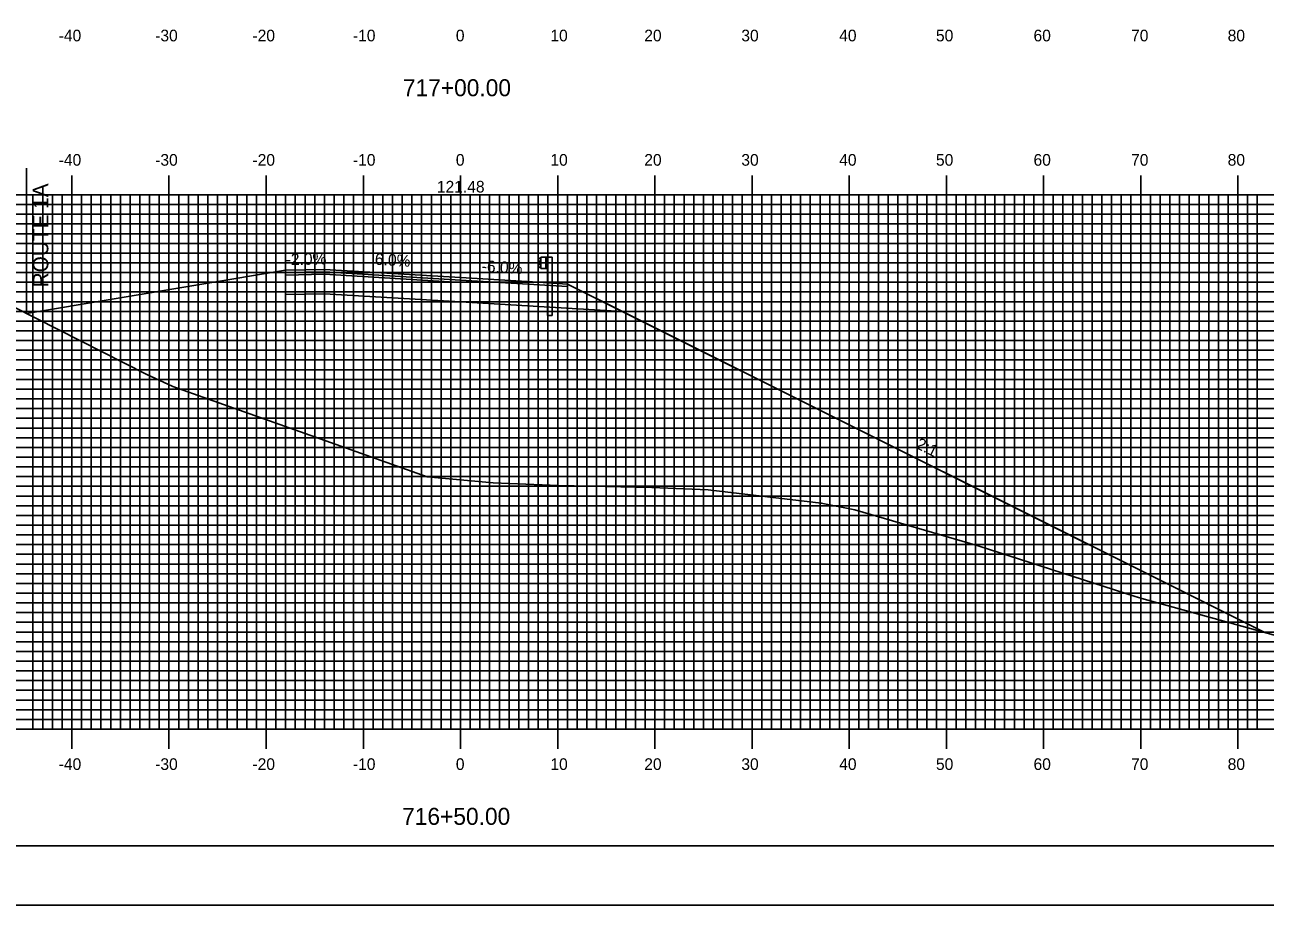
# Model space of a CAD drawing. Extents: x 856871 to 857214, y 364366 to 364586.
# Drawn here: x 856992 to 857119.6, y 364365.7 to 364456.3 of the extents above; entities that cross this region are included whole.
import ezdxf

# ---------------------------------------------------------------- set-up
doc = ezdxf.new("R2010")
doc.units = 0
for name, color, linetype in [('ANNOTATION', 7, 'Continuous'), ('BORDER', 7, 'Continuous'), ('D_Guardrail_Beam_Rt', 7, 'Continuous'), ('D_Roadway_Centerline', 7, 'Continuous'), ('D_Roadway_Centerline_Text', 7, 'Continuous'), ('D_Roadway_Edge_Shoulder', 7, 'Continuous'), ('D_Roadway_Edge_TW', 7, 'Continuous'), ('D_Roadway_Pavement', 7, 'Continuous'), ('D_Roadway_SlopeLines', 7, 'Continuous'), ('D_Roadway_SubGrade', 7, 'Continuous'), ('H_V ANNOTATION', 7, 'Continuous'), ('MAJOR', 7, 'Continuous'), ('MINOR', 7, 'Continuous'), ('PLOT BOUNDARY', 7, 'Continuous'), ('S_Roadway_Centerline', 7, 'Continuous')]:
    doc.layers.add(name, color=color, linetype=linetype)

msp = doc.modelspace()

# ---------------------------------------------------------------- linework, layer by layer
at = {"layer": 'BORDER'}
msp.add_lwpolyline([(856887.22, 364371.79), (857207.22, 364371.79), (857207.22, 364581.79), (856887.22, 364581.79)], close=True, dxfattribs=at)
at = {"layer": 'D_Guardrail_Beam_Rt'}
for p, q in [((857045, 364432.27), (857044.86, 364432.17)), ((857045.09, 364432.29), (857045.02, 364432.27)), ((857045.09, 364432.37), (857045.78, 364432.37)), ((857045.09, 364431.2), (857045.09, 364432.37)), ((857045.61, 364432.37), (857045.61, 364431.2)), ((857045.72, 364432.37), (857045.72, 364431.2)), ((857045.78, 364432.37), (857046.25, 364432.37)), ((857045.78, 364432.37), (857045.78, 364431.2)), ((857046.25, 364432.37), (857046.25, 364426.37)), ((857044.86, 364432.02), (857045.06, 364431.89)), ((857045.06, 364431.69), (857044.86, 364431.55)), ((857044.86, 364431.41), (857045, 364431.31)), ((857045.02, 364431.3), (857045.09, 364431.29)), ((857045.09, 364431.82), (857045.09, 364431.75)), ((857045.78, 364431.2), (857045.09, 364431.2)), ((857045.76, 364426.37), (857045.76, 364431.2)), ((857045.76, 364426.37), (857046.25, 364426.37))]:
    msp.add_line(p, q, dxfattribs=at)
for centre, major_axis, start_param, end_param in [((857045.03, 364432.23), (-0.0417, 0), 4.907132, 5.323254), ((857044.91, 364432.09), (-0.0877, 0), 5.323254, 7.243116), ((857044.91, 364431.48), (-0.0877, 0), 5.323254, 7.243116), ((857045.03, 364431.34), (-0.0417, 0), 0.959931, 1.376053), ((857045.01, 364431.82), (0.0789, 0), 0, 0.959931), ((857045.01, 364431.75), (0.0789, 0), 5.323254, 6.283185)]:
    msp.add_ellipse(centre, major_axis=major_axis, ratio=0.995501, start_param=start_param, end_param=end_param, dxfattribs=at)
at = {"layer": 'D_Roadway_Centerline'}
msp.add_lwpolyline([(857018.82, 364431.03), (857022.82, 364431.11), (857036.82, 364430.27), (857044.82, 364429.79), (857047.82, 364429.61), (857053.5, 364426.77), (857119.44, 364393.8)], dxfattribs=at)
at = {"layer": 'D_Roadway_Edge_Shoulder'}
for points in [[(857022.82, 364431.11), (857018.82, 364431.03), (857018.82, 364430.78), (857022.82, 364430.86)], [(857036.82, 364430.27), (857044.82, 364429.79), (857044.82, 364429.79), (857047.82, 364429.61), (857047.82, 364429.36), (857036.82, 364430.02)]]:
    msp.add_lwpolyline(points, close=True, dxfattribs=at)
at = {"layer": 'D_Roadway_Edge_TW'}
msp.add_lwpolyline([(857022.82, 364431.11), (857036.82, 364430.27), (857036.82, 364430.02), (857022.82, 364430.86)], close=True, dxfattribs=at)
at = {"layer": 'D_Roadway_Pavement'}
for points in [[(857022.82, 364430.86), (857018.82, 364430.78), (857018.82, 364430.53), (857022.82, 364430.61)], [(857022.82, 364430.86), (857036.82, 364430.02), (857036.82, 364429.77), (857022.82, 364430.61)]]:
    msp.add_lwpolyline(points, close=True, dxfattribs=at)
msp.add_lwpolyline([(857036.82, 364430.02), (857036.82, 364429.77)], dxfattribs=at)
msp.add_lwpolyline([(857036.82, 364430.02), (857036.82, 364429.77)], dxfattribs=at)
at = {"layer": 'D_Roadway_SlopeLines'}
for points in [[(857018.82, 364431.03), (856992.14, 364426.58)], [(857047.82, 364429.61), (857119.44, 364393.8)]]:
    msp.add_lwpolyline(points, dxfattribs=at)
at = {"layer": 'D_Roadway_SubGrade'}
msp.add_line((856992.14, 364441.54), (856992.14, 364426.58), dxfattribs=at)
for points in [[(857022.82, 364430.61), (857018.82, 364430.53), (857018.82, 364430.78), (857018.82, 364431.03), (857018.82, 364428.53), (857022.82, 364428.61)], [(857022.82, 364430.61), (857036.82, 364429.77), (857036.82, 364427.77), (857022.82, 364428.61)], [(857036.82, 364429.77), (857036.82, 364430.02), (857047.82, 364429.36), (857047.82, 364429.61), (857053.5, 364426.77), (857036.82, 364427.77)]]:
    msp.add_lwpolyline(points, close=True, dxfattribs=at)
at = {"layer": 'MAJOR'}
for p, q in [((856996.82, 364440.79), (856996.82, 364438.79)), ((857006.82, 364440.79), (857006.82, 364438.79)), ((857016.82, 364440.79), (857016.82, 364438.79)), ((857026.82, 364440.79), (857026.82, 364438.79)), ((857036.82, 364440.79), (857036.82, 364438.79)), ((857046.82, 364440.79), (857046.82, 364438.79)), ((857056.82, 364440.79), (857056.82, 364438.79)), ((857066.82, 364440.79), (857066.82, 364438.79)), ((857076.82, 364440.79), (857076.82, 364438.79)), ((857086.82, 364440.79), (857086.82, 364438.79)), ((857096.82, 364440.79), (857096.82, 364438.79)), ((857106.82, 364440.79), (857106.82, 364438.79)), ((857116.82, 364440.79), (857116.82, 364438.79)), ((856896.82, 364438.79), (857176.82, 364438.79)), ((856896.82, 364438.79), (857176.82, 364438.79)), ((856996.82, 364383.79), (856996.82, 364438.79)), ((857006.82, 364383.79), (857006.82, 364438.79)), ((857016.82, 364383.79), (857016.82, 364438.79)), ((857026.82, 364383.79), (857026.82, 364438.79)), ((857036.82, 364383.79), (857036.82, 364438.79)), ((857046.82, 364383.79), (857046.82, 364438.79)), ((857056.82, 364383.79), (857056.82, 364438.79)), ((857066.82, 364383.79), (857066.82, 364438.79)), ((857076.82, 364383.79), (857076.82, 364438.79)), ((857086.82, 364383.79), (857086.82, 364438.79)), ((857096.82, 364383.79), (857096.82, 364438.79)), ((857106.82, 364383.79), (857106.82, 364438.79)), ((857116.82, 364383.79), (857116.82, 364438.79)), ((856896.82, 364433.79), (857176.82, 364433.79)), ((856896.82, 364428.79), (857176.82, 364428.79)), ((856896.82, 364423.79), (857176.82, 364423.79)), ((856896.82, 364418.79), (857176.82, 364418.79)), ((856896.82, 364413.79), (857176.82, 364413.79)), ((856896.82, 364408.79), (857176.82, 364408.79)), ((856896.82, 364403.79), (857176.82, 364403.79)), ((856896.82, 364398.79), (857176.82, 364398.79)), ((856896.82, 364393.79), (857176.82, 364393.79)), ((856896.82, 364388.79), (857176.82, 364388.79)), ((856896.82, 364383.79), (857176.82, 364383.79)), ((856896.82, 364383.79), (857176.82, 364383.79)), ((856996.82, 364381.78), (856996.82, 364383.79)), ((857006.82, 364381.78), (857006.82, 364383.79)), ((857016.82, 364381.78), (857016.82, 364383.79)), ((857026.82, 364381.78), (857026.82, 364383.79)), ((857036.82, 364381.78), (857036.82, 364383.79)), ((857046.82, 364381.78), (857046.82, 364383.79)), ((857056.82, 364381.78), (857056.82, 364383.79)), ((857066.82, 364381.78), (857066.82, 364383.79)), ((857076.82, 364381.78), (857076.82, 364383.79)), ((857086.82, 364381.78), (857086.82, 364383.79)), ((857096.82, 364381.78), (857096.82, 364383.79)), ((857106.82, 364381.78), (857106.82, 364383.79)), ((857116.82, 364381.78), (857116.82, 364383.79))]:
    msp.add_line(p, q, dxfattribs=at)
at = {"layer": 'MINOR'}
for p, q in [((856992.82, 364383.79), (856992.82, 364438.79)), ((856993.82, 364383.79), (856993.82, 364438.79)), ((856994.82, 364383.79), (856994.82, 364438.79)), ((856995.82, 364383.79), (856995.82, 364438.79)), ((856997.82, 364383.79), (856997.82, 364438.79)), ((856998.82, 364383.79), (856998.82, 364438.79)), ((856999.82, 364383.79), (856999.82, 364438.79)), ((857000.82, 364383.79), (857000.82, 364438.79)), ((857001.82, 364383.79), (857001.82, 364438.79)), ((857002.82, 364383.79), (857002.82, 364438.79)), ((857003.82, 364383.79), (857003.82, 364438.79)), ((857004.82, 364383.79), (857004.82, 364438.79)), ((857005.82, 364383.79), (857005.82, 364438.79)), ((857007.82, 364383.79), (857007.82, 364438.79)), ((857008.82, 364383.79), (857008.82, 364438.79)), ((857009.82, 364383.79), (857009.82, 364438.79)), ((857010.82, 364383.79), (857010.82, 364438.79)), ((857011.82, 364383.79), (857011.82, 364438.79)), ((857012.82, 364383.79), (857012.82, 364438.79)), ((857013.82, 364383.79), (857013.82, 364438.79)), ((857014.82, 364383.79), (857014.82, 364438.79)), ((857015.82, 364383.79), (857015.82, 364438.79)), ((857017.82, 364383.79), (857017.82, 364438.79)), ((857018.82, 364383.79), (857018.82, 364438.79)), ((857019.82, 364383.79), (857019.82, 364438.79)), ((857020.82, 364383.79), (857020.82, 364438.79)), ((857021.82, 364383.79), (857021.82, 364438.79)), ((857022.82, 364383.79), (857022.82, 364438.79)), ((857023.82, 364383.79), (857023.82, 364438.79)), ((857024.82, 364383.79), (857024.82, 364438.79)), ((857025.82, 364383.79), (857025.82, 364438.79)), ((857027.82, 364383.79), (857027.82, 364438.79)), ((857028.82, 364383.79), (857028.82, 364438.79)), ((857029.82, 364383.79), (857029.82, 364438.79)), ((857030.82, 364383.79), (857030.82, 364438.79)), ((857031.82, 364383.79), (857031.82, 364438.79)), ((857032.82, 364383.79), (857032.82, 364438.79)), ((857033.82, 364383.79), (857033.82, 364438.79)), ((857034.82, 364383.79), (857034.82, 364438.79)), ((857035.82, 364383.79), (857035.82, 364438.79)), ((857037.82, 364383.79), (857037.82, 364438.79)), ((857038.82, 364383.79), (857038.82, 364438.79)), ((857039.82, 364383.79), (857039.82, 364438.79)), ((857040.82, 364383.79), (857040.82, 364438.79)), ((857041.82, 364383.79), (857041.82, 364438.79)), ((857042.82, 364383.79), (857042.82, 364438.79)), ((857043.82, 364383.79), (857043.82, 364438.79)), ((857044.82, 364383.79), (857044.82, 364438.79)), ((857045.82, 364383.79), (857045.82, 364438.79)), ((857047.82, 364383.79), (857047.82, 364438.79)), ((857048.82, 364383.79), (857048.82, 364438.79)), ((857049.82, 364383.79), (857049.82, 364438.79)), ((857050.82, 364383.79), (857050.82, 364438.79)), ((857051.82, 364383.79), (857051.82, 364438.79)), ((857052.82, 364383.79), (857052.82, 364438.79)), ((857053.82, 364383.79), (857053.82, 364438.79)), ((857054.82, 364383.79), (857054.82, 364438.79)), ((857055.82, 364383.79), (857055.82, 364438.79)), ((857057.82, 364383.79), (857057.82, 364438.79)), ((857058.82, 364383.79), (857058.82, 364438.79)), ((857059.82, 364383.79), (857059.82, 364438.79)), ((857060.82, 364383.79), (857060.82, 364438.79)), ((857061.82, 364383.79), (857061.82, 364438.79)), ((857062.82, 364383.79), (857062.82, 364438.79)), ((857063.82, 364383.79), (857063.82, 364438.79)), ((857064.82, 364383.79), (857064.82, 364438.79)), ((857065.82, 364383.79), (857065.82, 364438.79)), ((857067.82, 364383.79), (857067.82, 364438.79)), ((857068.82, 364383.79), (857068.82, 364438.79)), ((857069.82, 364383.79), (857069.82, 364438.79)), ((857070.82, 364383.79), (857070.82, 364438.79)), ((857071.82, 364383.79), (857071.82, 364438.79)), ((857072.82, 364383.79), (857072.82, 364438.79)), ((857073.82, 364383.79), (857073.82, 364438.79)), ((857074.82, 364383.79), (857074.82, 364438.79)), ((857075.82, 364383.79), (857075.82, 364438.79)), ((857077.82, 364383.79), (857077.82, 364438.79)), ((857078.82, 364383.79), (857078.82, 364438.79)), ((857079.82, 364383.79), (857079.82, 364438.79)), ((857080.82, 364383.79), (857080.82, 364438.79)), ((857081.82, 364383.79), (857081.82, 364438.79)), ((857082.82, 364383.79), (857082.82, 364438.79)), ((857083.82, 364383.79), (857083.82, 364438.79)), ((857084.82, 364383.79), (857084.82, 364438.79)), ((857085.82, 364383.79), (857085.82, 364438.79)), ((857087.82, 364383.79), (857087.82, 364438.79)), ((857088.82, 364383.79), (857088.82, 364438.79)), ((857089.82, 364383.79), (857089.82, 364438.79)), ((857090.82, 364383.79), (857090.82, 364438.79)), ((857091.82, 364383.79), (857091.82, 364438.79)), ((857092.82, 364383.79), (857092.82, 364438.79)), ((857093.82, 364383.79), (857093.82, 364438.79)), ((857094.82, 364383.79), (857094.82, 364438.79)), ((857095.82, 364383.79), (857095.82, 364438.79)), ((857097.82, 364383.79), (857097.82, 364438.79)), ((857098.82, 364383.79), (857098.82, 364438.79)), ((857099.82, 364383.79), (857099.82, 364438.79)), ((857100.82, 364383.79), (857100.82, 364438.79)), ((857101.82, 364383.79), (857101.82, 364438.79)), ((857102.82, 364383.79), (857102.82, 364438.79)), ((857103.82, 364383.79), (857103.82, 364438.79)), ((857104.82, 364383.79), (857104.82, 364438.79)), ((857105.82, 364383.79), (857105.82, 364438.79)), ((857107.82, 364383.79), (857107.82, 364438.79)), ((857108.82, 364383.79), (857108.82, 364438.79)), ((857109.82, 364383.79), (857109.82, 364438.79)), ((857110.82, 364383.79), (857110.82, 364438.79)), ((857111.82, 364383.79), (857111.82, 364438.79)), ((857112.82, 364383.79), (857112.82, 364438.79)), ((857113.82, 364383.79), (857113.82, 364438.79)), ((857114.82, 364383.79), (857114.82, 364438.79)), ((857115.82, 364383.79), (857115.82, 364438.79)), ((857117.82, 364383.79), (857117.82, 364438.79)), ((857118.82, 364383.79), (857118.82, 364438.79)), ((856896.82, 364437.79), (857176.82, 364437.79)), ((856896.82, 364436.79), (857176.82, 364436.79)), ((856896.82, 364435.79), (857176.82, 364435.79)), ((856896.82, 364434.79), (857176.82, 364434.79)), ((856896.82, 364432.79), (857176.82, 364432.79)), ((856896.82, 364431.79), (857176.82, 364431.79)), ((856896.82, 364430.79), (857176.82, 364430.79)), ((856896.82, 364429.79), (857176.82, 364429.79)), ((856896.82, 364427.79), (857176.82, 364427.79)), ((856896.82, 364426.79), (857176.82, 364426.79)), ((856896.82, 364425.79), (857176.82, 364425.79)), ((856896.82, 364424.79), (857176.82, 364424.79)), ((856896.82, 364422.79), (857176.82, 364422.79)), ((856896.82, 364421.79), (857176.82, 364421.79)), ((856896.82, 364420.79), (857176.82, 364420.79)), ((856896.82, 364419.79), (857176.82, 364419.79)), ((856896.82, 364417.79), (857176.82, 364417.79)), ((856896.82, 364416.79), (857176.82, 364416.79)), ((856896.82, 364415.79), (857176.82, 364415.79)), ((856896.82, 364414.79), (857176.82, 364414.79)), ((856896.82, 364412.79), (857176.82, 364412.79)), ((856896.82, 364411.79), (857176.82, 364411.79)), ((856896.82, 364410.79), (857176.82, 364410.79)), ((856896.82, 364409.79), (857176.82, 364409.79)), ((856896.82, 364407.79), (857176.82, 364407.79)), ((856896.82, 364406.79), (857176.82, 364406.79)), ((856896.82, 364405.79), (857176.82, 364405.79)), ((856896.82, 364404.79), (857176.82, 364404.79)), ((856896.82, 364402.79), (857176.82, 364402.79)), ((856896.82, 364401.79), (857176.82, 364401.79)), ((856896.82, 364400.79), (857176.82, 364400.79)), ((856896.82, 364399.79), (857176.82, 364399.79)), ((856896.82, 364397.79), (857176.82, 364397.79)), ((856896.82, 364396.79), (857176.82, 364396.79)), ((856896.82, 364395.79), (857176.82, 364395.79)), ((856896.82, 364394.79), (857176.82, 364394.79)), ((856896.82, 364392.79), (857176.82, 364392.79)), ((856896.82, 364391.79), (857176.82, 364391.79)), ((856896.82, 364390.79), (857176.82, 364390.79)), ((856896.82, 364389.79), (857176.82, 364389.79)), ((856896.82, 364387.79), (857176.82, 364387.79)), ((856896.82, 364386.79), (857176.82, 364386.79)), ((856896.82, 364385.79), (857176.82, 364385.79)), ((856896.82, 364384.79), (857176.82, 364384.79))]:
    msp.add_line(p, q, dxfattribs=at)
at = {"layer": 'PLOT BOUNDARY'}
msp.add_lwpolyline([(856871.04, 364365.67), (857211.04, 364365.67), (857211.04, 364585.67), (856871.04, 364585.67)], close=True, dxfattribs=at)
at = {"layer": 'S_Roadway_Centerline'}
msp.add_lwpolyline([(856990.89, 364427.22), (857004.48, 364420.33), (857007.22, 364419.07), (857010.9, 364417.77), (857033.4, 364409.76), (857040.17, 364409.15), (857046.91, 364408.87), (857056.51, 364408.65), (857062.29, 364408.41), (857073.95, 364407.06), (857077.41, 364406.35), (857090.08, 364402.66), (857106.24, 364397.44), (857106.48, 364397.36), (857106.94, 364397.24), (857121.46, 364393.24)], dxfattribs=at)

# ---------------------------------------------------------------- texts
at = {"layer": 'ANNOTATION'}
for s, height, rotation, p in [('ROUTE 1A', 1.6, 90, (856994.4, 364429.27)), ('-2.0%', 1.2, 1.1458, (857018.84, 364431.55)), ('6.0%', 1.2, 356.5664, (857027.98, 364431.6)), ('-6.0%', 1.2, 356.5664, (857038.98, 364430.87)), ('2:1', 1.2, 333.4349, (857083.57, 364412.77))]:
    msp.add_text(s, height=height, rotation=rotation, dxfattribs=at).set_placement(p)
at = {"layer": 'D_Roadway_Centerline_Text'}
msp.add_text('121.48', height=1.2, dxfattribs=at).set_placement((857034.39, 364439.03))
at = {"layer": 'H_V ANNOTATION'}
for s, height, p in [('-40', 1.2, (856995.47, 364454.59)), ('-30', 1.2, (857005.4, 364454.59)), ('-20', 1.2, (857015.41, 364454.59)), ('-10', 1.2, (857025.75, 364454.59)), ('0', 1.2, (857036.34, 364454.59)), ('10', 1.2, (857046.07, 364454.59)), ('20', 1.2, (857055.73, 364454.59)), ('30', 1.2, (857065.72, 364454.59)), ('40', 1.2, (857075.79, 364454.59)), ('50', 1.2, (857085.75, 364454.59)), ('60', 1.2, (857095.79, 364454.59)), ('70', 1.2, (857105.83, 364454.59)), ('80', 1.2, (857115.77, 364454.59)), ('717+00.00', 1.75, (857030.89, 364448.94)), ('-40', 1.2, (856995.47, 364441.79)), ('-30', 1.2, (857005.4, 364441.79)), ('-20', 1.2, (857015.41, 364441.79)), ('-10', 1.2, (857025.75, 364441.79)), ('0', 1.2, (857036.34, 364441.79)), ('10', 1.2, (857046.07, 364441.79)), ('20', 1.2, (857055.73, 364441.79)), ('30', 1.2, (857065.72, 364441.79)), ('40', 1.2, (857075.79, 364441.79)), ('50', 1.2, (857085.75, 364441.79)), ('60', 1.2, (857095.79, 364441.79)), ('70', 1.2, (857105.83, 364441.79)), ('80', 1.2, (857115.77, 364441.79)), ('-40', 1.2, (856995.47, 364379.59)), ('-30', 1.2, (857005.4, 364379.59)), ('-20', 1.2, (857015.41, 364379.59)), ('-10', 1.2, (857025.75, 364379.59)), ('0', 1.2, (857036.34, 364379.59)), ('10', 1.2, (857046.07, 364379.59)), ('20', 1.2, (857055.73, 364379.59)), ('30', 1.2, (857065.72, 364379.59)), ('40', 1.2, (857075.79, 364379.59)), ('50', 1.2, (857085.75, 364379.59)), ('60', 1.2, (857095.79, 364379.59)), ('70', 1.2, (857105.83, 364379.59)), ('80', 1.2, (857115.77, 364379.59)), ('716+50.00', 1.75, (857030.81, 364373.94))]:
    msp.add_text(s, height=height, dxfattribs=at).set_placement(p)

doc.saveas('drawing.dxf')
